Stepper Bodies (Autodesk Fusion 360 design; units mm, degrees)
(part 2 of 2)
sketch "SlothChair" plane through (0, 0, 0) normal (0, 0, 1) x axis (1, 0, 0)
  line L1 (30, 0) -> (0, 0)
  line L2 (30, 30) -> (30, 0)
  line L3 (0, 30) -> (30, 30)
  line L4 (0, 0) -> (0, 30)
  line L5 (5, 0) -> (0, 0)
  line L6 (5, 5) -> (5, 0)
  line L7 (0, 5) -> (5, 5)
  line L8 (0, 0) -> (0, 5)
  line L9 (25, 5) -> (5, 5)
  line L10 (25, 25) -> (25, 5)
  line L11 (5, 25) -> (25, 25)
  line L12 (5, 5) -> (5, 25)
  line L13 (40, 5) -> (40, 25)
  line L14 (60, 5) -> (40, 5)
  line L15 (60, 25) -> (60, 5)
  line L16 (35, 30) -> (65, 30)
  line L17 (65, 30) -> (65, 0)
  line L18 (40, 0) -> (35, 0)
  line L19 (35, 5) -> (40, 5)
  line L20 (40, 25) -> (60, 25)
  line L21 (35, 0) -> (35, 30)
  line L22 (40, 5) -> (40, 0)
  line L23 (35, 0) -> (35, 5)
  line L24 (65, 0) -> (35, 0)
  point P1 (0, 0)
  point P2 (0, 0)
  point P3 (30, 0)
  point P5 (0, 30)
  point P6 (5, 0)
  point P8 (0, 5)
  point P7 (5, 5)
  point P9 (25, 5)
  point P11 (5, 25)
  point P12 (65, 0)
  point P15 (35, 0)
  point P14 (35, 30)
  point P21 (40, 0)
  point P16 (35, 5)
  point P19 (60, 5)
  point P20 (40, 5)
  point P18 (40, 25)
  horizontal L1
  vertical L2
  horizontal L3
  vertical L4
  coincident P1 P2
  horizontal L5
  vertical L6
  horizontal L7
  vertical L8
  horizontal L9
  vertical L10
  horizontal L11
  vertical L12
  horizontal L24
  vertical L17
  horizontal L16
  vertical L21
  horizontal L18
  vertical L22
  horizontal L19
  vertical L23
  horizontal L14
  vertical L15
  horizontal L20
  vertical L13
  dimension "d200" distance P2 P3 = 30
  dimension "d201" distance P2 P5 = 30
  dimension "d202" distance P2 P6 = 5
  dimension "d203" distance P2 P8 = 5
  dimension "d204" distance P7 P9 = 20
  dimension "d205" distance P7 P11 = 20
  dimension "d206" distance P12 P15 = 30
  dimension "d207" distance P14 P15 = 30
  dimension "d208" distance P15 P21 = 5
  dimension "d209" distance P15 P16 = 5
  dimension "d210" distance P19 P20 = 20
  dimension "d211" distance P18 P20 = 20
sketch "Covers" plane through (0, 0, 0) normal (0, 0, 1) x axis (1, 0, 0)
  line L1 (-3, 241) -> (83, 241)
  line L2 (83, 241) -> (-3, 241)
  line L3 (83, 253) -> (83, 241)
  line L4 (-3, 253) -> (83, 253)
  line L5 (-3, 241) -> (-3, 253)
  line L6 (-3, 231) -> (-3, 241)
  line L7 (83, 231) -> (-3, 231)
  line L8 (83, 186) -> (83, 231)
  line L9 (-3, 186) -> (83, 186)
  line L10 (-3, 231) -> (-3, 186)
  point P3 (-3, 241)
  point P4 (-3, 241)
  point P7 (-3, 253)
  point P8 (-3, 231)
  point P9 (83, 231)
  point P11 (-3, 186)
  horizontal L2
  vertical L3
  horizontal L4
  vertical L5
  coincident P3 P4
  perpendicular L1 L6
  horizontal L7
  vertical L8
  horizontal L9
  vertical L10
  dimension "d213" distance P4 P7 = 12
  dimension "d214" distance P4 P8 = 10
  dimension "d215" distance P8 P9 = 86
  dimension "d216" distance P8 P11 = 45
